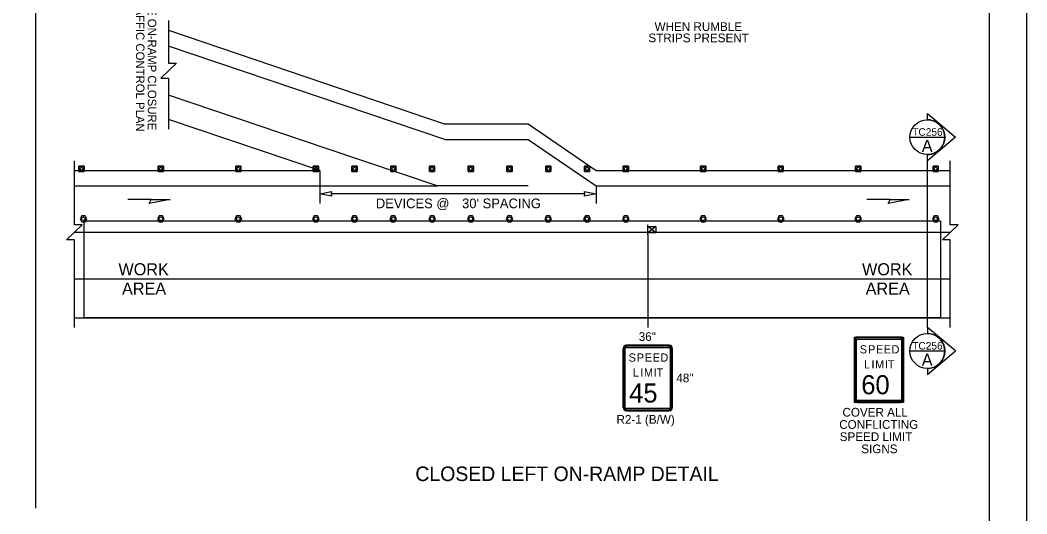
# Model space of a CAD drawing. Extents: x 99999 to 100116, y 99995 to 100013.
# Drawn here: x 100087.75 to 100096.06, y 100001.53 to 100005.61 of the extents above; entities that cross this region are included whole.
import ezdxf

# ---------------------------------------------------------------- set-up
doc = ezdxf.new("R2010")
doc.units = 0
for name, color, linetype in [('RD_MK_LineEdgeYellow', 7, 'Continuous'), ('RD_MK_LineLane', 7, 'Continuous'), ('SH_DE_DetailHeading2Text', 7, 'Continuous'), ('SH_GI_PlotLimits', 7, 'Continuous'), ('SH_GI_SectionCut', 7, 'Continuous'), ('SH_GI_SheetBorder', 7, 'Continuous'), ('TR_SN_ConstructionSigns', 7, 'Continuous'), ('TR_WZ_PortableSignMount5ftMinBlk-Wht', 7, 'Continuous'), ('TR_WZ_TallChanDevice', 7, 'Continuous'), ('TR_WZ_TrafficCone', 7, 'Continuous'), ('TR_WZ_WorkAreaLabel', 7, 'Continuous'), ('TR_WZ_WorkZoneDetails', 7, 'Continuous'), ('TR_WZ_WorkZoneTextCurrent', 7, 'Continuous')]:
    doc.layers.add(name, color=color, linetype=linetype)

msp = doc.modelspace()

# ---------------------------------------------------------------- linework, layer by layer
at = {"layer": 'RD_MK_LineEdgeYellow'}
for p, q in [((100091.2543, 100004.622), (100088.9733, 100005.3922)), ((100090.2818, 100004.545), (100088.9733, 100004.9869)), ((100091.2543, 100004.622), (100091.9445, 100004.622)), ((100091.9445, 100004.622), (100092.5055, 100004.238)), ((100088.195, 100004.238), (100090.2214, 100004.238)), ((100092.5055, 100004.238), (100095.43, 100004.238)), ((100088.195, 100003.47), (100095.43, 100003.47))]:
    msp.add_line(p, q, dxfattribs=at)
at = {"layer": 'RD_MK_LineLane'}
for points in [[(100091.9445, 100004.238), (100091.1912, 100004.238)], [(100095.43, 100003.854), (100088.195, 100003.854)]]:
    msp.add_lwpolyline(points, dxfattribs=at)
at = {"layer": 'SH_GI_PlotLimits'}
msp.add_lwpolyline([(100079.0625, 99999.6875), (100096.0625, 99999.6875), (100096.0625, 100010.6875), (100079.0625, 100010.6875)], close=True, dxfattribs=at)
at = {"layer": 'SH_GI_SectionCut'}
for p, q in [((100095.2407, 100004.7848), (100095.2407, 100004.8357)), ((100095.2407, 100004.8357), (100095.4733, 100004.6408)), ((100095.4733, 100004.6408), (100095.2407, 100004.446)), ((100095.2407, 100004.446), (100095.2407, 100004.4968)), ((100095.2407, 100003.0699), (100095.2407, 100004.446)), ((100095.2407, 100003.07), (100095.2407, 100003.0191)), ((100095.4733, 100002.8751), (100095.2407, 100003.07)), ((100095.2407, 100002.6802), (100095.4733, 100002.8751)), ((100095.2407, 100002.7311), (100095.2407, 100002.6802))]:
    msp.add_line(p, q, dxfattribs=at)
for points in [[(100095.0967, 100004.6408), (100095.3847, 100004.6408)], [(100095.0967, 100002.8751), (100095.3847, 100002.8751)]]:
    msp.add_lwpolyline(points, dxfattribs=at)
for centre in [(100095.2407, 100004.6408), (100095.2407, 100002.8751)]:
    msp.add_circle(centre, 0.144, dxfattribs=at)
for centre in [(100095.2407, 100004.6408), (100095.2407, 100002.8751)]:
    msp.add_arc(centre, 0.144, 269.99779, 90.00221, dxfattribs=at)
at = {"layer": 'SH_GI_SheetBorder'}
msp.add_line((100095.75, 100010.375), (100095.75, 100000), dxfattribs=at)
at = {"layer": 'TR_SN_ConstructionSigns'}
for p, q in [((100094.6633, 100002.99), (100095.0177, 100002.99)), ((100095.0177, 100002.99), (100094.6633, 100002.99)), ((100095.0177, 100002.9829), (100094.6633, 100002.9829)), ((100094.6633, 100002.9731), (100095.0177, 100002.9731)), ((100092.729, 100002.4073), (100092.729, 100002.8966)), ((100092.729, 100002.8966), (100092.729, 100002.4073)), ((100092.736, 100002.8966), (100092.736, 100002.4073)), ((100092.7458, 100002.4073), (100092.7458, 100002.8966)), ((100092.7543, 100002.922), (100093.1086, 100002.922)), ((100093.1086, 100002.922), (100092.7543, 100002.922)), ((100093.1086, 100002.9149), (100092.7543, 100002.9149)), ((100092.7543, 100002.9051), (100093.1086, 100002.9051)), ((100093.1171, 100002.8966), (100093.1171, 100002.4073)), ((100093.1269, 100002.4073), (100093.1269, 100002.8966)), ((100093.134, 100002.8966), (100093.134, 100002.4073)), ((100093.134, 100002.4073), (100093.134, 100002.8966)), ((100094.638, 100002.4753), (100094.638, 100002.9646)), ((100094.638, 100002.9646), (100094.638, 100002.4753)), ((100094.6451, 100002.9646), (100094.6451, 100002.4753)), ((100094.6549, 100002.4753), (100094.6549, 100002.9646)), ((100095.0261, 100002.9646), (100095.0261, 100002.4753)), ((100095.036, 100002.4753), (100095.036, 100002.9646)), ((100095.043, 100002.9646), (100095.043, 100002.4753)), ((100095.043, 100002.4753), (100095.043, 100002.9646)), ((100093.1086, 100002.3988), (100092.7543, 100002.3988)), ((100095.0177, 100002.4668), (100094.6633, 100002.4668)), ((100094.6633, 100002.457), (100095.0177, 100002.457)), ((100095.0177, 100002.45), (100094.6633, 100002.45)), ((100094.6633, 100002.45), (100095.0177, 100002.45)), ((100092.7543, 100002.389), (100093.1086, 100002.389)), ((100093.1086, 100002.382), (100092.7543, 100002.382)), ((100092.7543, 100002.382), (100093.1086, 100002.382))]:
    msp.add_line(p, q, dxfattribs=at)
msp.add_lwpolyline([(100094.638, 100002.99), (100095.043, 100002.99), (100095.043, 100002.45), (100094.638, 100002.45)], close=True, dxfattribs=at)
for centre, radius, start, end in [((100094.6633, 100002.9646), 0.0253, 90, 180), ((100094.6633, 100002.9646), 0.0253, 90, 180), ((100094.6633, 100002.9646), 0.0183, 90, 180), ((100094.6633, 100002.9646), 0.00844, 90, 180), ((100095.0177, 100002.9646), 0.0253, 0, 90), ((100095.0177, 100002.9646), 0.0253, 360, 90), ((100095.0177, 100002.9646), 0.0183, 0, 90), ((100095.0177, 100002.9646), 0.00844, 360, 90), ((100092.7543, 100002.8966), 0.0253, 90, 180), ((100092.7543, 100002.8966), 0.0253, 90, 180), ((100092.7543, 100002.8966), 0.0183, 90, 180), ((100092.7543, 100002.8966), 0.00844, 90, 180), ((100093.1086, 100002.8966), 0.0253, 360, 90), ((100093.1086, 100002.8966), 0.0253, 360, 90), ((100093.1086, 100002.8966), 0.0183, 0, 90), ((100093.1086, 100002.8966), 0.00844, 360, 90), ((100094.6633, 100002.4753), 0.0253, 180, 270), ((100094.6633, 100002.4753), 0.0253, 180, 270), ((100094.6633, 100002.4753), 0.0183, 180, 270), ((100094.6633, 100002.4753), 0.00844, 180, 270), ((100095.0177, 100002.4753), 0.0253, 270, 0), ((100095.0177, 100002.4753), 0.0183, 270, 360), ((100095.0177, 100002.4753), 0.00844, 270, 0), ((100095.0177, 100002.4753), 0.0253, 270, 0), ((100092.7543, 100002.4073), 0.0253, 180, 270), ((100092.7543, 100002.4073), 0.0253, 180, 270), ((100092.7543, 100002.4073), 0.0183, 180, 270), ((100092.7543, 100002.4073), 0.00844, 180, 270), ((100093.1086, 100002.4073), 0.0253, 270, 360), ((100093.1086, 100002.4073), 0.0183, 270, 360), ((100093.1086, 100002.4073), 0.00844, 270, 0), ((100093.1086, 100002.4073), 0.0253, 270, 360)]:
    msp.add_arc(centre, radius, start, end, dxfattribs=at)
at = {"layer": 'TR_WZ_PortableSignMount5ftMinBlk-Wht'}
for p, q in [((100092.9315, 100003.838), (100092.9315, 100003.918)), ((100092.9982, 100003.904), (100092.9315, 100003.852)), ((100092.9982, 100003.852), (100092.9315, 100003.904)), ((100092.9648, 100003.878), (100092.9648, 100003.878)), ((100092.9649, 100003.878), (100092.9649, 100003.878))]:
    msp.add_line(p, q, dxfattribs=at)
msp.add_lwpolyline([(100092.9982, 100003.904), (100092.9982, 100003.852), (100092.9315, 100003.852), (100092.9315, 100003.904)], close=True, dxfattribs=at)
at = {"layer": 'TR_WZ_TallChanDevice'}
for points in [[(100088.2833, 100003.9909), (100088.2555, 100003.9909), (100088.2417, 100003.9669), (100088.2555, 100003.9429), (100088.2833, 100003.9429), (100088.2971, 100003.9669)], [(100088.9233, 100003.9909), (100088.8955, 100003.9909), (100088.8817, 100003.9669), (100088.8955, 100003.9429), (100088.9233, 100003.9429), (100088.9371, 100003.9669)], [(100089.5633, 100003.9909), (100089.5355, 100003.9909), (100089.5217, 100003.9669), (100089.5355, 100003.9429), (100089.5633, 100003.9429), (100089.5771, 100003.9669)], [(100090.2033, 100003.9909), (100090.1755, 100003.9909), (100090.1617, 100003.9669), (100090.1755, 100003.9429), (100090.2033, 100003.9429), (100090.2171, 100003.9669)], [(100090.5233, 100003.9909), (100090.4955, 100003.9909), (100090.4817, 100003.9669), (100090.4955, 100003.9429), (100090.5233, 100003.9429), (100090.5371, 100003.9669)], [(100090.8433, 100003.9909), (100090.8155, 100003.9909), (100090.8017, 100003.9669), (100090.8155, 100003.9429), (100090.8433, 100003.9429), (100090.8571, 100003.9669)], [(100091.1633, 100003.9909), (100091.1355, 100003.9909), (100091.1217, 100003.9669), (100091.1355, 100003.9429), (100091.1633, 100003.9429), (100091.1771, 100003.9669)], [(100091.4833, 100003.9909), (100091.4555, 100003.9909), (100091.4417, 100003.9669), (100091.4555, 100003.9429), (100091.4833, 100003.9429), (100091.4971, 100003.9669)], [(100091.8033, 100003.9909), (100091.7755, 100003.9909), (100091.7617, 100003.9669), (100091.7755, 100003.9429), (100091.8033, 100003.9429), (100091.8171, 100003.9669)], [(100092.1233, 100003.9909), (100092.0955, 100003.9909), (100092.0817, 100003.9669), (100092.0955, 100003.9429), (100092.1233, 100003.9429), (100092.1371, 100003.9669)], [(100092.4433, 100003.9909), (100092.4155, 100003.9909), (100092.4017, 100003.9669), (100092.4155, 100003.9429), (100092.4433, 100003.9429), (100092.4571, 100003.9669)], [(100092.7633, 100003.9909), (100092.7355, 100003.9909), (100092.7217, 100003.9669), (100092.7355, 100003.9429), (100092.7633, 100003.9429), (100092.7771, 100003.9669)], [(100093.4033, 100003.9909), (100093.3755, 100003.9909), (100093.3617, 100003.9669), (100093.3755, 100003.9429), (100093.4033, 100003.9429), (100093.4171, 100003.9669)], [(100094.0433, 100003.9909), (100094.0155, 100003.9909), (100094.0017, 100003.9669), (100094.0155, 100003.9429), (100094.0433, 100003.9429), (100094.0571, 100003.9669)], [(100094.6833, 100003.9909), (100094.6555, 100003.9909), (100094.6417, 100003.9669), (100094.6555, 100003.9429), (100094.6833, 100003.9429), (100094.6971, 100003.9669)], [(100095.3233, 100003.9909), (100095.2955, 100003.9909), (100095.2817, 100003.9669), (100095.2955, 100003.9429), (100095.3233, 100003.9429), (100095.3371, 100003.9669)]]:
    msp.add_lwpolyline(points, close=True, dxfattribs=at)
for points in [[(100088.2833, 100003.9909), (100088.2555, 100003.9909), (100088.2417, 100003.9669), (100088.2555, 100003.9429), (100088.2833, 100003.9429), (100088.2971, 100003.9669), (100088.2833, 100003.9909)], [(100088.9233, 100003.9909), (100088.8955, 100003.9909), (100088.8817, 100003.9669), (100088.8955, 100003.9429), (100088.9233, 100003.9429), (100088.9371, 100003.9669), (100088.9233, 100003.9909)], [(100089.5633, 100003.9909), (100089.5355, 100003.9909), (100089.5217, 100003.9669), (100089.5355, 100003.9429), (100089.5633, 100003.9429), (100089.5771, 100003.9669), (100089.5633, 100003.9909)], [(100090.2033, 100003.9909), (100090.1755, 100003.9909), (100090.1617, 100003.9669), (100090.1755, 100003.9429), (100090.2033, 100003.9429), (100090.2171, 100003.9669), (100090.2033, 100003.9909)], [(100090.5233, 100003.9909), (100090.4955, 100003.9909), (100090.4817, 100003.9669), (100090.4955, 100003.9429), (100090.5233, 100003.9429), (100090.5371, 100003.9669), (100090.5233, 100003.9909)], [(100090.8433, 100003.9909), (100090.8155, 100003.9909), (100090.8017, 100003.9669), (100090.8155, 100003.9429), (100090.8433, 100003.9429), (100090.8571, 100003.9669), (100090.8433, 100003.9909)], [(100091.1633, 100003.9909), (100091.1355, 100003.9909), (100091.1217, 100003.9669), (100091.1355, 100003.9429), (100091.1633, 100003.9429), (100091.1771, 100003.9669), (100091.1633, 100003.9909)], [(100091.4833, 100003.9909), (100091.4555, 100003.9909), (100091.4417, 100003.9669), (100091.4555, 100003.9429), (100091.4833, 100003.9429), (100091.4971, 100003.9669), (100091.4833, 100003.9909)], [(100091.8033, 100003.9909), (100091.7755, 100003.9909), (100091.7617, 100003.9669), (100091.7755, 100003.9429), (100091.8033, 100003.9429), (100091.8171, 100003.9669), (100091.8033, 100003.9909)], [(100092.1233, 100003.9909), (100092.0955, 100003.9909), (100092.0817, 100003.9669), (100092.0955, 100003.9429), (100092.1233, 100003.9429), (100092.1371, 100003.9669), (100092.1233, 100003.9909)], [(100092.4433, 100003.9909), (100092.4155, 100003.9909), (100092.4017, 100003.9669), (100092.4155, 100003.9429), (100092.4433, 100003.9429), (100092.4571, 100003.9669), (100092.4433, 100003.9909)], [(100092.7633, 100003.9909), (100092.7355, 100003.9909), (100092.7217, 100003.9669), (100092.7355, 100003.9429), (100092.7633, 100003.9429), (100092.7771, 100003.9669), (100092.7633, 100003.9909)], [(100093.4033, 100003.9909), (100093.3755, 100003.9909), (100093.3617, 100003.9669), (100093.3755, 100003.9429), (100093.4033, 100003.9429), (100093.4171, 100003.9669), (100093.4033, 100003.9909)], [(100094.0433, 100003.9909), (100094.0155, 100003.9909), (100094.0017, 100003.9669), (100094.0155, 100003.9429), (100094.0433, 100003.9429), (100094.0571, 100003.9669), (100094.0433, 100003.9909)], [(100094.6833, 100003.9909), (100094.6555, 100003.9909), (100094.6417, 100003.9669), (100094.6555, 100003.9429), (100094.6833, 100003.9429), (100094.6971, 100003.9669), (100094.6833, 100003.9909)], [(100095.3233, 100003.9909), (100095.2955, 100003.9909), (100095.2817, 100003.9669), (100095.2955, 100003.9429), (100095.3233, 100003.9429), (100095.3371, 100003.9669), (100095.3233, 100003.9909)]]:
    msp.add_lwpolyline(points, dxfattribs=at)
for centre in [(100088.2694, 100003.9669), (100088.9094, 100003.9669), (100089.5494, 100003.9669), (100090.1894, 100003.9669), (100090.5094, 100003.9669), (100090.8294, 100003.9669), (100091.1494, 100003.9669), (100091.4694, 100003.9669), (100091.7894, 100003.9669), (100092.1094, 100003.9669), (100092.4294, 100003.9669), (100092.7494, 100003.9669), (100093.3894, 100003.9669), (100094.0294, 100003.9669), (100094.6694, 100003.9669), (100095.3094, 100003.9669)]:
    msp.add_circle(centre, 0.015, dxfattribs=at)
at = {"layer": 'TR_WZ_TrafficCone'}
for points in [[(100088.2326, 100004.358), (100088.2753, 100004.358), (100088.2753, 100004.4006), (100088.2326, 100004.4006), (100088.2326, 100004.358)], [(100088.2326, 100004.4006), (100088.2753, 100004.4006), (100088.2753, 100004.358), (100088.2326, 100004.358), (100088.2326, 100004.4006)], [(100088.8881, 100004.358), (100088.9307, 100004.358), (100088.9307, 100004.4006), (100088.8881, 100004.4006), (100088.8881, 100004.358)], [(100088.8881, 100004.4006), (100088.9307, 100004.4006), (100088.9307, 100004.358), (100088.8881, 100004.358), (100088.8881, 100004.4006)], [(100089.5281, 100004.358), (100089.5707, 100004.358), (100089.5707, 100004.4006), (100089.5281, 100004.4006), (100089.5281, 100004.358)], [(100089.5281, 100004.4006), (100089.5707, 100004.4006), (100089.5707, 100004.358), (100089.5281, 100004.358), (100089.5281, 100004.4006)], [(100090.1681, 100004.358), (100090.2107, 100004.358), (100090.2107, 100004.4006), (100090.1681, 100004.4006), (100090.1681, 100004.358)], [(100090.1681, 100004.4006), (100090.2107, 100004.4006), (100090.2107, 100004.358), (100090.1681, 100004.358), (100090.1681, 100004.4006)], [(100090.4881, 100004.358), (100090.5307, 100004.358), (100090.5307, 100004.4006), (100090.4881, 100004.4006), (100090.4881, 100004.358)], [(100090.4881, 100004.4006), (100090.5307, 100004.4006), (100090.5307, 100004.358), (100090.4881, 100004.358), (100090.4881, 100004.4006)], [(100090.8081, 100004.358), (100090.8507, 100004.358), (100090.8507, 100004.4006), (100090.8081, 100004.4006), (100090.8081, 100004.358)], [(100090.8081, 100004.4006), (100090.8507, 100004.4006), (100090.8507, 100004.358), (100090.8081, 100004.358), (100090.8081, 100004.4006)], [(100091.1281, 100004.358), (100091.1707, 100004.358), (100091.1707, 100004.4006), (100091.1281, 100004.4006), (100091.1281, 100004.358)], [(100091.1281, 100004.4006), (100091.1707, 100004.4006), (100091.1707, 100004.358), (100091.1281, 100004.358), (100091.1281, 100004.4006)], [(100091.4481, 100004.358), (100091.4907, 100004.358), (100091.4907, 100004.4006), (100091.4481, 100004.4006), (100091.4481, 100004.358)], [(100091.4481, 100004.4006), (100091.4907, 100004.4006), (100091.4907, 100004.358), (100091.4481, 100004.358), (100091.4481, 100004.4006)], [(100091.7681, 100004.358), (100091.8107, 100004.358), (100091.8107, 100004.4006), (100091.7681, 100004.4006), (100091.7681, 100004.358)], [(100091.7681, 100004.4006), (100091.8107, 100004.4006), (100091.8107, 100004.358), (100091.7681, 100004.358), (100091.7681, 100004.4006)], [(100092.0881, 100004.358), (100092.1307, 100004.358), (100092.1307, 100004.4006), (100092.0881, 100004.4006), (100092.0881, 100004.358)], [(100092.0881, 100004.4006), (100092.1307, 100004.4006), (100092.1307, 100004.358), (100092.0881, 100004.358), (100092.0881, 100004.4006)], [(100092.4081, 100004.358), (100092.4507, 100004.358), (100092.4507, 100004.4006), (100092.4081, 100004.4006), (100092.4081, 100004.358)], [(100092.4081, 100004.4006), (100092.4507, 100004.4006), (100092.4507, 100004.358), (100092.4081, 100004.358), (100092.4081, 100004.4006)], [(100092.7281, 100004.358), (100092.7707, 100004.358), (100092.7707, 100004.4006), (100092.7281, 100004.4006), (100092.7281, 100004.358)], [(100092.7281, 100004.4006), (100092.7707, 100004.4006), (100092.7707, 100004.358), (100092.7281, 100004.358), (100092.7281, 100004.4006)], [(100093.3681, 100004.358), (100093.4107, 100004.358), (100093.4107, 100004.4006), (100093.3681, 100004.4006), (100093.3681, 100004.358)], [(100093.3681, 100004.4006), (100093.4107, 100004.4006), (100093.4107, 100004.358), (100093.3681, 100004.358), (100093.3681, 100004.4006)], [(100094.0081, 100004.358), (100094.0507, 100004.358), (100094.0507, 100004.4006), (100094.0081, 100004.4006), (100094.0081, 100004.358)], [(100094.0081, 100004.4006), (100094.0507, 100004.4006), (100094.0507, 100004.358), (100094.0081, 100004.358), (100094.0081, 100004.4006)], [(100094.6481, 100004.358), (100094.6907, 100004.358), (100094.6907, 100004.4006), (100094.6481, 100004.4006), (100094.6481, 100004.358)], [(100094.6481, 100004.4006), (100094.6907, 100004.4006), (100094.6907, 100004.358), (100094.6481, 100004.358), (100094.6481, 100004.4006)], [(100095.2881, 100004.358), (100095.3307, 100004.358), (100095.3307, 100004.4006), (100095.2881, 100004.4006), (100095.2881, 100004.358)], [(100095.2881, 100004.4006), (100095.3307, 100004.4006), (100095.3307, 100004.358), (100095.2881, 100004.358), (100095.2881, 100004.4006)]]:
    msp.add_lwpolyline(points, dxfattribs=at)
for centre in [(100088.2539, 100004.3793), (100088.9094, 100004.3793), (100089.5494, 100004.3793), (100090.1894, 100004.3793), (100090.5094, 100004.3793), (100090.8294, 100004.3793), (100091.1494, 100004.3793), (100091.4694, 100004.3793), (100091.7894, 100004.3793), (100092.1094, 100004.3793), (100092.4294, 100004.3793), (100092.7494, 100004.3793), (100093.3894, 100004.3793), (100094.0294, 100004.3793), (100094.6694, 100004.3793), (100095.3094, 100004.3793)]:
    msp.add_circle(centre, 0.0133, dxfattribs=at)
at = {"layer": 'TR_WZ_WorkZoneDetails'}
for p, q in [((100087.875, 100008.9181), (100087.875, 100001.5759)), ((100088.9733, 100005.5235), (100091.2488, 100004.75)), ((100090.2214, 100004.366), (100088.9733, 100004.7871)), ((100091.2488, 100004.75), (100091.9445, 100004.75)), ((100091.9445, 100004.75), (100092.5055, 100004.366)), ((100091.1912, 100004.238), (100090.2818, 100004.545)), ((100088.195, 100004.366), (100090.2214, 100004.366)), ((100090.2214, 100004.366), (100090.2214, 100004.094)), ((100092.5055, 100004.366), (100095.43, 100004.366)), ((100090.2214, 100004.238), (100091.1912, 100004.238)), ((100092.5055, 100004.238), (100092.5055, 100004.094)), ((100092.4118, 100004.174), (100090.3151, 100004.174)), ((100088.83, 100004.1249), (100088.6371, 100004.1249)), ((100094.9336, 100004.1249), (100094.7408, 100004.1249)), ((100092.9315, 100003.838), (100092.9315, 100003.07)), ((100088.195, 100003.15), (100095.43, 100003.15))]:
    msp.add_line(p, q, dxfattribs=at)
for points in [[(100088.9733, 100005.6039), (100088.9733, 100005.2515), (100089.0373, 100005.2515), (100088.9092, 100005.1276), (100088.9733, 100005.1276), (100088.9733, 100004.7071)], [(100088.195, 100003.07), (100088.195, 100003.792), (100088.131, 100003.792), (100088.259, 100003.9159), (100088.195, 100003.9159), (100088.195, 100004.446)], [(100095.43, 100003.07), (100095.43, 100003.792), (100095.366, 100003.792), (100095.494, 100003.9159), (100095.43, 100003.9159), (100095.43, 100004.446)]]:
    msp.add_lwpolyline(points, dxfattribs=at)
for points in [[(100090.2214, 100004.174), (100090.3196, 100004.1932), (100090.3151, 100004.174), (100090.3196, 100004.1547)], [(100092.5055, 100004.174), (100092.4073, 100004.1547), (100092.4118, 100004.174), (100092.4073, 100004.1932)], [(100088.9872, 100004.1249), (100088.8122, 100004.0941), (100088.83, 100004.1249)], [(100095.0909, 100004.1249), (100094.9158, 100004.0941), (100094.9336, 100004.1249)], [(100088.275, 100003.15), (100088.275, 100003.95), (100095.35, 100003.95), (100095.35, 100003.15)]]:
    msp.add_lwpolyline(points, close=True, dxfattribs=at)

# ---------------------------------------------------------------- texts
at = {"layer": 'SH_DE_DetailHeading2Text'}
msp.add_text('CLOSED LEFT ON-RAMP DETAIL', height=0.12, rotation=360, dxfattribs=at).set_placement((100091.0116, 100001.8009))
at = {"layer": 'SH_GI_SectionCut'}
for p in [(100095.1158, 100004.6524), (100095.1158, 100002.8867)]:
    msp.add_text('TC256', height=0.0625, dxfattribs=at).set_placement(p)
for p in [(100095.1945, 100004.5188), (100095.1945, 100002.7531)]:
    msp.add_text('A', height=0.1, rotation=359.99005, dxfattribs=at).set_placement(p)
at = {"layer": 'TR_SN_ConstructionSigns'}
for s, height, p in [('WHEN RUMBLE', 0.072, (100092.9875, 100005.5184)), ('STRIPS PRESENT', 0.072, (100092.9365, 100005.4247)), ('36"', 0.072, (100092.8567, 100002.958)), ('S', 0.0675, (100092.7728, 100002.787)), ('P', 0.0675, (100092.841, 100002.787)), ('E', 0.0675, (100092.9072, 100002.787)), ('E', 0.0675, (100092.9713, 100002.787)), ('D', 0.0675, (100093.0354, 100002.787)), ('L', 0.0675, (100092.8079, 100002.6632)), ('I', 0.0675, (100092.87, 100002.6632)), ('M', 0.0675, (100092.8997, 100002.6632)), ('I', 0.0675, (100092.9807, 100002.6632)), ('T', 0.0675, (100093.0044, 100002.6632)), ('48"', 0.072, (100093.1672, 100002.616)), ('R2-1 (B/W)', 0.072, (100092.6727, 100002.274))]:
    msp.add_text(s, height=height, rotation=360, dxfattribs=at).set_placement(p)
for s, height, p in [('S', 0.0675, (100094.6819, 100002.855)), ('P', 0.0675, (100094.7501, 100002.855)), ('E', 0.0675, (100094.8162, 100002.855)), ('E', 0.0675, (100094.8803, 100002.855)), ('D', 0.0675, (100094.9445, 100002.855)), ('L', 0.0675, (100094.717, 100002.7312)), ('I', 0.0675, (100094.7791, 100002.7312)), ('M', 0.0675, (100094.8088, 100002.7312)), ('I', 0.0675, (100094.8898, 100002.7312)), ('T', 0.0675, (100094.9134, 100002.7312)), ('60', 0.1575, (100094.6949, 100002.5175)), ('45', 0.1575, (100092.778, 100002.4495)), ('COVER ALL', 0.072, (100094.5392, 100002.333)), ('CONFLICTING', 0.072, (100094.5128, 100002.2322)), ('SPEED LIMIT', 0.072, (100094.5168, 100002.1314)), ('SIGNS', 0.072, (100094.6947, 100002.0306))]:
    msp.add_text(s, height=height, dxfattribs=at).set_placement(p)
at = {"layer": 'TR_WZ_WorkAreaLabel'}
for s, p in [('WORK', (100088.559, 100003.5)), ('WORK', (100094.7013, 100003.5)), ('AREA', (100088.5887, 100003.34)), ('AREA', (100094.7309, 100003.34))]:
    msp.add_text(s, height=0.1, dxfattribs=at).set_placement(p)
at = {"layer": 'TR_WZ_WorkZoneTextCurrent'}
for s, p in [('TRAFFIC CONTROL PLAN', (100088.7037, 100005.8361)), ('SEE ON-RAMP CLOSURE', (100088.8017, 100005.8322))]:
    msp.add_text(s, height=0.07, rotation=270, dxfattribs=at).set_placement(p)
for s, p in [('DEVICES @', (100090.6853, 100004.054)), ("30' SPACING", (100091.3978, 100004.054))]:
    msp.add_text(s, height=0.08, dxfattribs=at).set_placement(p)

doc.saveas('drawing.dxf')
